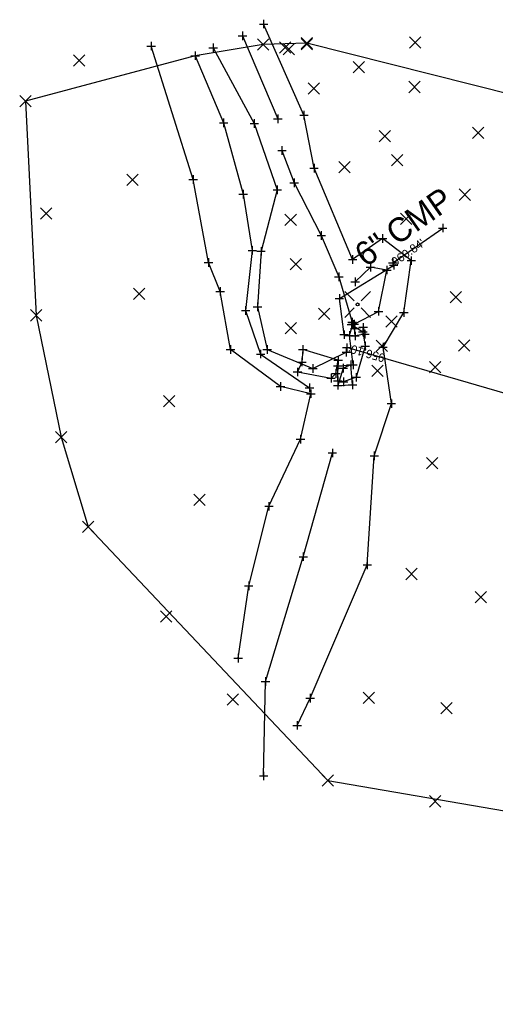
# Model space of a CAD drawing. Extents: x 160138 to 160780, y 488720 to 491073.
# Drawn here: x 160311.4 to 160367.2, y 489628.9 to 489744.3 of the extents above; entities that cross this region are included whole.
import ezdxf

# ---------------------------------------------------------------- set-up
doc = ezdxf.new("R2010")
doc.units = 0
for name, color, linetype in [('_CIVIL_CONSTRUCTION', 7, 'Continuous'), ('DR_X_Storm_Sewer', 7, 'Continuous'), ('DR_X_Text', 7, 'Continuous'), ('RD_X_Concrete_Pad', 7, 'Continuous'), ('RS_Raster1', 7, 'Continuous'), ('RW_X_CL_100_Bearings', 7, 'Continuous'), ('RW_X_CL_100_Stations', 7, 'Continuous'), ('SC_Scratch1', 7, 'Continuous'), ('SV_P_Control_Cells_Set', 7, 'Continuous'), ('SV_P_Mon_Cells_Set', 7, 'Continuous'), ('SV_X_Mon_Cells_Found', 7, 'Continuous'), ('SV_X_Random_Point', 7, 'Continuous'), ('SV_X_Terrain_Boundary', 7, 'Continuous')]:
    doc.layers.add(name, color=color, linetype=linetype)

msp = doc.modelspace()

# ---------------------------------------------------------------- linework, layer by layer
at = {"layer": '_CIVIL_CONSTRUCTION'}
for p, q in [((160339.33, 489740.77), (160340.67, 489742.1)), ((160339.33, 489742.1), (160340.67, 489740.77)), ((160344.44, 489740.93), (160345.77, 489742.26)), ((160344.44, 489742.26), (160345.77, 489740.93)), ((160344.45, 489740.81), (160345.79, 489742.14)), ((160344.45, 489742.14), (160345.79, 489740.81)), ((160357.15, 489741.01), (160358.48, 489742.35)), ((160357.15, 489742.35), (160358.48, 489741.01)), ((160341.91, 489740.44), (160343.25, 489741.77)), ((160341.91, 489741.77), (160343.25, 489740.44)), ((160342.34, 489740.23), (160343.67, 489741.57)), ((160342.34, 489741.57), (160343.67, 489740.23)), ((160317.74, 489738.89), (160319.08, 489740.22)), ((160317.74, 489740.22), (160319.08, 489738.89)), ((160350.55, 489738.12), (160351.89, 489739.46)), ((160350.55, 489739.46), (160351.89, 489738.12)), ((160345.26, 489735.61), (160346.59, 489736.94)), ((160345.26, 489736.94), (160346.59, 489735.61)), ((160357.09, 489735.79), (160358.42, 489737.13)), ((160357.09, 489737.13), (160358.42, 489735.79)), ((160311.44, 489734.13), (160312.77, 489735.46)), ((160311.44, 489735.46), (160312.77, 489734.13)), ((160364.56, 489730.41), (160365.89, 489731.75)), ((160364.56, 489731.75), (160365.89, 489730.41)), ((160353.6, 489730.03), (160354.94, 489731.36)), ((160353.6, 489731.36), (160354.94, 489730.03)), ((160355.03, 489727.22), (160356.37, 489728.55)), ((160355.03, 489728.55), (160356.37, 489727.22)), ((160348.88, 489726.4), (160350.21, 489727.73)), ((160348.88, 489727.73), (160350.21, 489726.4)), ((160323.99, 489724.93), (160325.32, 489726.26)), ((160323.99, 489726.26), (160325.32, 489724.93)), ((160362.99, 489723.17), (160364.32, 489724.51)), ((160362.99, 489724.51), (160364.32, 489723.17)), ((160313.87, 489720.98), (160315.2, 489722.31)), ((160313.87, 489722.31), (160315.2, 489720.98)), ((160342.55, 489720.24), (160343.89, 489721.57)), ((160342.55, 489721.57), (160343.89, 489720.24)), ((160356.09, 489720.33), (160357.42, 489721.67)), ((160356.09, 489721.67), (160357.42, 489720.33)), ((160343.15, 489715.03), (160344.49, 489716.37)), ((160343.15, 489716.37), (160344.49, 489715.03)), ((160324.77, 489711.56), (160326.1, 489712.9)), ((160324.77, 489712.9), (160326.1, 489711.56)), ((160361.94, 489711.16), (160363.27, 489712.49)), ((160361.94, 489712.49), (160363.27, 489711.16)), ((160312.69, 489709.04), (160314.02, 489710.37)), ((160312.69, 489710.37), (160314.02, 489709.04)), ((160346.47, 489709.21), (160347.8, 489710.55)), ((160346.47, 489710.55), (160347.8, 489709.21)), ((160354.39, 489708.31), (160355.72, 489709.65)), ((160354.39, 489709.65), (160355.72, 489708.31)), ((160342.58, 489707.53), (160343.91, 489708.86)), ((160342.58, 489708.86), (160343.91, 489707.53)), ((160353.25, 489705.47), (160354.58, 489706.81)), ((160353.25, 489706.81), (160354.58, 489705.47)), ((160362.89, 489705.51), (160364.22, 489706.84)), ((160362.89, 489706.84), (160364.22, 489705.51)), ((160352.74, 489702.54), (160354.07, 489703.88)), ((160352.74, 489703.88), (160354.07, 489702.54)), ((160359.51, 489702.97), (160360.84, 489704.3)), ((160359.51, 489704.3), (160360.84, 489702.97)), ((160328.3, 489698.99), (160329.64, 489700.32)), ((160328.3, 489700.32), (160329.64, 489698.99)), ((160315.62, 489694.76), (160316.96, 489696.09)), ((160315.62, 489696.09), (160316.96, 489694.76)), ((160359.14, 489691.72), (160360.48, 489693.06)), ((160359.14, 489693.06), (160360.48, 489691.72)), ((160331.86, 489687.41), (160333.19, 489688.74)), ((160331.86, 489688.74), (160333.19, 489687.41)), ((160318.81, 489684.26), (160320.14, 489685.6)), ((160318.81, 489685.6), (160320.14, 489684.26)), ((160356.71, 489678.73), (160358.05, 489680.06)), ((160356.71, 489680.06), (160358.05, 489678.73)), ((160364.87, 489676.02), (160366.2, 489677.36)), ((160364.87, 489677.36), (160366.2, 489676.02)), ((160327.96, 489673.74), (160329.29, 489675.07)), ((160327.96, 489675.07), (160329.29, 489673.74)), ((160335.76, 489664.03), (160337.1, 489665.37)), ((160335.76, 489665.37), (160337.1, 489664.03)), ((160351.73, 489664.21), (160353.06, 489665.54)), ((160351.73, 489665.54), (160353.06, 489664.21)), ((160360.83, 489663.01), (160362.16, 489664.34)), ((160360.83, 489664.34), (160362.16, 489663.01)), ((160346.9, 489654.53), (160348.23, 489655.87)), ((160346.9, 489655.87), (160348.23, 489654.53)), ((160359.49, 489652.09), (160360.82, 489653.43)), ((160359.49, 489653.43), (160360.82, 489652.09))]:
    msp.add_line(p, q, dxfattribs=at)
at = {"layer": 'DR_X_Storm_Sewer'}
for p, q in [((160355.2, 489715.85), (160361.05, 489719.93)), ((160416.53, 489686.63), (160349.81, 489705.92))]:
    msp.add_line(p, q, dxfattribs=at)
at = {"layer": 'RD_X_Concrete_Pad'}
msp.add_lwpolyline([(160347.95, 489702.35), (160348.52, 489702.88), (160348.8, 489704.46), (160344.64, 489705.72), (160344.53, 489704.23), (160344.01, 489703.07)], close=True, dxfattribs=at)
at = {"layer": 'RS_Raster1'}
for p, q in [((160360.55, 489719.93), (160361.55, 489719.93)), ((160361.05, 489720.43), (160361.05, 489719.43)), ((160361.05, 489719.93), (160361.05, 489719.93)), ((160354.7, 489715.85), (160355.7, 489715.85)), ((160355.2, 489716.35), (160355.2, 489715.35)), ((160355.2, 489715.85), (160355.2, 489715.85)), ((160349.81, 489706.42), (160349.81, 489705.42)), ((160349.31, 489705.92), (160350.31, 489705.92)), ((160349.81, 489705.92), (160349.81, 489705.92))]:
    msp.add_line(p, q, dxfattribs=at)
at = {"layer": 'RW_X_CL_100_Bearings'}
for points in [[(160350.77, 489707.29), (160350.72, 489708.17), (160351.73, 489708.3), (160351.93, 489707.49)], [(160349.37, 489703.52), (160348.75, 489701.5), (160350.46, 489701.56), (160350.27, 489703.9)]]:
    msp.add_lwpolyline(points, close=True, dxfattribs=at)
at = {"layer": 'RW_X_CL_100_Stations'}
msp.add_lwpolyline([(160350.35, 489708.64), (160351.68, 489707.77), (160351.95, 489706.08), (160350.9, 489702.44), (160349.43, 489701.91), (160348.74, 489702.04), (160348.75, 489703.79), (160350.53, 489703.91), (160350.1, 489707.34), (160350.52, 489708.65)], close=True, dxfattribs=at)
at = {"layer": 'SV_P_Control_Cells_Set'}
for points in [[(160343.99, 489661.66), (160345.5, 489664.84), (160352.21, 489680.48), (160353.03, 489693.23), (160355.03, 489699.36), (160354.05, 489705.99), (160356.49, 489710.03), (160357.37, 489716.11), (160353.98, 489718.71), (160350.49, 489716.24), (160345.96, 489726.95), (160344.78, 489733.16), (160340.05, 489743.84)], [(160337.56, 489742.45), (160341.71, 489732.74)], [(160337.06, 489669.53), (160338.3, 489678.01), (160340.67, 489687.33), (160344.38, 489695.18), (160345.59, 489700.52), (160342.03, 489701.36), (160336.17, 489705.71), (160334.96, 489712.51), (160333.59, 489715.9), (160331.79, 489725.62), (160326.86, 489741.26)], [(160332.02, 489740.13), (160335.36, 489732.25), (160337.64, 489723.89), (160338.72, 489717.32), (160337.94, 489710.28), (160339.7, 489705.17), (160345.42, 489701.2)], [(160342.2, 489729.01), (160343.62, 489725.24), (160346.81, 489719.05), (160348.86, 489714.22), (160350.44, 489708.92)], [(160350.68, 489708.66), (160353.52, 489710.17), (160354.49, 489715.01), (160352.57, 489715.35), (160350.79, 489713.62)]]:
    msp.add_lwpolyline(points, dxfattribs=at)
at = {"layer": 'SV_P_Mon_Cells_Set'}
for points in [[(160334.14, 489741.04), (160338.95, 489732.19), (160341.65, 489724.41), (160339.74, 489717.21), (160339.32, 489710.69), (160340.46, 489705.7), (160345.81, 489703.48), (160349.74, 489705.38)], [(160349.5, 489707.44), (160348.93, 489711.69), (160355.3, 489715.57)], [(160340.05, 489655.73), (160340.26, 489666.8), (160344.7, 489681.42), (160348.11, 489693.58)]]:
    msp.add_lwpolyline(points, dxfattribs=at)
at = {"layer": 'SV_X_Mon_Cells_Found'}
for p, q in [((160349.56, 489712.49), (160350.65, 489711.4)), ((160351.49, 489711.4), (160352.58, 489712.49)), ((160349.56, 489709.47), (160350.65, 489710.57)), ((160351.49, 489710.57), (160352.58, 489709.47))]:
    msp.add_line(p, q, dxfattribs=at)
msp.add_circle((160351.07, 489710.99), 0.17, dxfattribs=at)
at = {"layer": 'SV_X_Random_Point'}
for p, q in [((160340.05, 489744.34), (160340.05, 489743.34)), ((160339.55, 489743.84), (160340.55, 489743.84)), ((160340.05, 489743.84), (160340.05, 489743.84)), ((160337.06, 489742.45), (160338.06, 489742.45)), ((160337.56, 489742.95), (160337.56, 489741.95)), ((160337.56, 489742.45), (160337.56, 489742.45)), ((160326.36, 489741.26), (160327.36, 489741.26)), ((160326.86, 489741.76), (160326.86, 489740.76)), ((160326.86, 489741.26), (160326.86, 489741.26)), ((160333.64, 489741.04), (160334.64, 489741.04)), ((160334.14, 489741.54), (160334.14, 489740.54)), ((160334.14, 489741.04), (160334.14, 489741.04)), ((160331.52, 489740.13), (160332.52, 489740.13)), ((160332.02, 489740.63), (160332.02, 489739.63)), ((160332.02, 489740.13), (160332.02, 489740.13)), ((160335.36, 489732.75), (160335.36, 489731.75)), ((160338.95, 489732.69), (160338.95, 489731.69)), ((160341.21, 489732.74), (160342.21, 489732.74)), ((160341.71, 489733.24), (160341.71, 489732.24)), ((160341.71, 489732.74), (160341.71, 489732.74)), ((160344.28, 489733.16), (160345.28, 489733.16)), ((160344.78, 489733.66), (160344.78, 489732.66)), ((160344.78, 489733.16), (160344.78, 489733.16)), ((160334.86, 489732.25), (160335.86, 489732.25)), ((160335.36, 489732.25), (160335.36, 489732.25)), ((160338.45, 489732.19), (160339.45, 489732.19)), ((160338.95, 489732.19), (160338.95, 489732.19)), ((160342.2, 489729.51), (160342.2, 489728.51)), ((160341.7, 489729.01), (160342.7, 489729.01)), ((160342.2, 489729.01), (160342.2, 489729.01)), ((160345.46, 489726.95), (160346.46, 489726.95)), ((160345.96, 489727.45), (160345.96, 489726.45)), ((160345.96, 489726.95), (160345.96, 489726.95)), ((160331.79, 489726.12), (160331.79, 489725.12)), ((160343.62, 489725.74), (160343.62, 489724.74)), ((160331.29, 489725.62), (160332.29, 489725.62)), ((160331.79, 489725.62), (160331.79, 489725.62)), ((160341.65, 489724.91), (160341.65, 489723.91)), ((160343.12, 489725.24), (160344.12, 489725.24)), ((160343.62, 489725.24), (160343.62, 489725.24)), ((160337.14, 489723.89), (160338.14, 489723.89)), ((160337.64, 489724.39), (160337.64, 489723.39)), ((160337.64, 489723.89), (160337.64, 489723.89)), ((160341.15, 489724.41), (160342.15, 489724.41)), ((160341.65, 489724.41), (160341.65, 489724.41)), ((160346.31, 489719.05), (160347.31, 489719.05)), ((160346.81, 489719.55), (160346.81, 489718.55)), ((160346.81, 489719.05), (160346.81, 489719.05)), ((160353.98, 489719.21), (160353.98, 489718.21)), ((160338.72, 489717.82), (160338.72, 489716.82)), ((160339.74, 489717.71), (160339.74, 489716.71)), ((160353.48, 489718.71), (160354.48, 489718.71)), ((160353.98, 489718.71), (160353.98, 489718.71)), ((160338.22, 489717.32), (160339.22, 489717.32)), ((160338.72, 489717.32), (160338.72, 489717.32)), ((160339.24, 489717.21), (160340.24, 489717.21)), ((160339.74, 489717.21), (160339.74, 489717.21)), ((160350.49, 489716.74), (160350.49, 489715.74)), ((160357.37, 489716.61), (160357.37, 489715.61)), ((160333.09, 489715.9), (160334.09, 489715.9)), ((160333.59, 489716.4), (160333.59, 489715.4)), ((160333.59, 489715.9), (160333.59, 489715.9)), ((160349.99, 489716.24), (160350.99, 489716.24)), ((160350.49, 489716.24), (160350.49, 489716.24)), ((160352.07, 489715.35), (160353.07, 489715.35)), ((160352.57, 489715.85), (160352.57, 489714.85)), ((160352.57, 489715.35), (160352.57, 489715.35)), ((160354.49, 489715.51), (160354.49, 489714.51)), ((160354.8, 489715.57), (160355.8, 489715.57)), ((160355.3, 489716.07), (160355.3, 489715.07)), ((160355.3, 489715.57), (160355.3, 489715.57)), ((160356.87, 489716.11), (160357.87, 489716.11)), ((160357.37, 489716.11), (160357.37, 489716.11)), ((160348.36, 489714.22), (160349.36, 489714.22)), ((160348.86, 489714.72), (160348.86, 489713.72)), ((160348.86, 489714.22), (160348.86, 489714.22)), ((160353.99, 489715.01), (160354.99, 489715.01)), ((160354.49, 489715.01), (160354.49, 489715.01)), ((160334.96, 489713.01), (160334.96, 489712.01)), ((160350.29, 489713.62), (160351.29, 489713.62)), ((160350.79, 489714.12), (160350.79, 489713.12)), ((160350.79, 489713.62), (160350.79, 489713.62)), ((160334.46, 489712.51), (160335.46, 489712.51)), ((160334.96, 489712.51), (160334.96, 489712.51)), ((160348.93, 489712.19), (160348.93, 489711.19)), ((160337.94, 489710.78), (160337.94, 489709.78)), ((160338.82, 489710.69), (160339.82, 489710.69)), ((160339.32, 489711.19), (160339.32, 489710.19)), ((160339.32, 489710.69), (160339.32, 489710.69)), ((160348.43, 489711.69), (160349.43, 489711.69)), ((160348.93, 489711.69), (160348.93, 489711.69)), ((160353.52, 489710.67), (160353.52, 489709.67)), ((160337.44, 489710.28), (160338.44, 489710.28)), ((160337.94, 489710.28), (160337.94, 489710.28)), ((160353.02, 489710.17), (160354.02, 489710.17)), ((160353.52, 489710.17), (160353.52, 489710.17)), ((160355.99, 489710.03), (160356.99, 489710.03)), ((160356.49, 489710.53), (160356.49, 489709.53)), ((160356.49, 489710.03), (160356.49, 489710.03)), ((160349.85, 489708.64), (160350.85, 489708.64)), ((160349.94, 489708.92), (160350.94, 489708.92)), ((160350.02, 489708.65), (160351.02, 489708.65)), ((160350.18, 489708.66), (160351.18, 489708.66)), ((160350.35, 489709.14), (160350.35, 489708.14)), ((160350.35, 489708.64), (160350.35, 489708.64)), ((160350.44, 489709.42), (160350.44, 489708.42)), ((160350.44, 489708.92), (160350.44, 489708.92)), ((160350.52, 489709.15), (160350.52, 489708.15)), ((160350.52, 489708.65), (160350.52, 489708.65)), ((160350.68, 489709.16), (160350.68, 489708.16)), ((160350.68, 489708.66), (160350.68, 489708.66)), ((160350.72, 489708.67), (160350.72, 489707.67)), ((160351.73, 489708.8), (160351.73, 489707.8)), ((160349, 489707.44), (160350, 489707.44)), ((160349.5, 489707.94), (160349.5, 489706.94)), ((160349.5, 489707.44), (160349.5, 489707.44)), ((160349.6, 489707.34), (160350.6, 489707.34)), ((160350.1, 489707.84), (160350.1, 489706.84)), ((160350.1, 489707.34), (160350.1, 489707.34)), ((160350.22, 489708.17), (160351.22, 489708.17)), ((160350.27, 489707.29), (160351.27, 489707.29)), ((160350.72, 489708.17), (160350.72, 489708.17)), ((160350.77, 489707.79), (160350.77, 489706.79)), ((160350.77, 489707.29), (160350.77, 489707.29)), ((160351.18, 489707.77), (160352.18, 489707.77)), ((160351.23, 489708.3), (160352.23, 489708.3)), ((160351.43, 489707.49), (160352.43, 489707.49)), ((160351.68, 489708.27), (160351.68, 489707.27)), ((160351.68, 489707.77), (160351.68, 489707.77)), ((160351.73, 489708.3), (160351.73, 489708.3)), ((160351.93, 489707.99), (160351.93, 489706.99)), ((160351.93, 489707.49), (160351.93, 489707.49)), ((160336.17, 489706.21), (160336.17, 489705.21)), ((160340.46, 489706.2), (160340.46, 489705.2)), ((160344.64, 489706.22), (160344.64, 489705.22)), ((160351.45, 489706.08), (160352.45, 489706.08)), ((160351.95, 489706.58), (160351.95, 489705.58)), ((160351.95, 489706.08), (160351.95, 489706.08)), ((160354.05, 489706.49), (160354.05, 489705.49)), ((160335.67, 489705.71), (160336.67, 489705.71)), ((160336.17, 489705.71), (160336.17, 489705.71)), ((160339.2, 489705.17), (160340.2, 489705.17)), ((160339.7, 489705.67), (160339.7, 489704.67)), ((160339.7, 489705.17), (160339.7, 489705.17)), ((160339.96, 489705.7), (160340.96, 489705.7)), ((160340.46, 489705.7), (160340.46, 489705.7)), ((160344.14, 489705.72), (160345.14, 489705.72)), ((160344.64, 489705.72), (160344.64, 489705.72)), ((160348.8, 489704.96), (160348.8, 489703.96)), ((160349.24, 489705.38), (160350.24, 489705.38)), ((160349.74, 489705.88), (160349.74, 489704.88)), ((160349.74, 489705.38), (160349.74, 489705.38)), ((160353.55, 489705.99), (160354.55, 489705.99)), ((160354.05, 489705.99), (160354.05, 489705.99)), ((160344.03, 489704.23), (160345.03, 489704.23)), ((160344.53, 489704.73), (160344.53, 489703.73)), ((160344.53, 489704.23), (160344.53, 489704.23)), ((160345.81, 489703.98), (160345.81, 489702.98)), ((160348.25, 489703.79), (160349.25, 489703.79)), ((160348.3, 489704.46), (160349.3, 489704.46)), ((160348.75, 489704.29), (160348.75, 489703.29)), ((160348.75, 489703.79), (160348.75, 489703.79)), ((160348.8, 489704.46), (160348.8, 489704.46)), ((160349.37, 489704.02), (160349.37, 489703.02)), ((160349.77, 489703.9), (160350.77, 489703.9)), ((160350.03, 489703.91), (160351.03, 489703.91)), ((160350.27, 489704.4), (160350.27, 489703.4)), ((160350.27, 489703.9), (160350.27, 489703.9)), ((160350.53, 489704.41), (160350.53, 489703.41)), ((160350.53, 489703.91), (160350.53, 489703.91)), ((160343.51, 489703.07), (160344.51, 489703.07)), ((160344.01, 489703.57), (160344.01, 489702.57)), ((160344.01, 489703.07), (160344.01, 489703.07)), ((160345.31, 489703.48), (160346.31, 489703.48)), ((160345.81, 489703.48), (160345.81, 489703.48)), ((160347.95, 489702.85), (160347.95, 489701.85)), ((160348.02, 489702.88), (160349.02, 489702.88)), ((160348.52, 489703.38), (160348.52, 489702.38)), ((160348.52, 489702.88), (160348.52, 489702.88)), ((160348.87, 489703.52), (160349.87, 489703.52)), ((160349.37, 489703.52), (160349.37, 489703.52)), ((160350.9, 489702.94), (160350.9, 489701.94)), ((160342.03, 489701.86), (160342.03, 489700.86)), ((160345.42, 489701.7), (160345.42, 489700.7)), ((160347.45, 489702.35), (160348.45, 489702.35)), ((160347.95, 489702.35), (160347.95, 489702.35)), ((160348.24, 489702.04), (160349.24, 489702.04)), ((160348.25, 489701.5), (160349.25, 489701.5)), ((160348.74, 489702.54), (160348.74, 489701.54)), ((160348.74, 489702.04), (160348.74, 489702.04)), ((160348.75, 489702), (160348.75, 489701)), ((160348.75, 489701.5), (160348.75, 489701.5)), ((160348.93, 489701.91), (160349.93, 489701.91)), ((160349.43, 489702.41), (160349.43, 489701.41)), ((160349.43, 489701.91), (160349.43, 489701.91)), ((160349.96, 489701.56), (160350.96, 489701.56)), ((160350.4, 489702.44), (160351.4, 489702.44)), ((160350.46, 489702.06), (160350.46, 489701.06)), ((160350.46, 489701.56), (160350.46, 489701.56)), ((160350.9, 489702.44), (160350.9, 489702.44)), ((160341.53, 489701.36), (160342.53, 489701.36)), ((160342.03, 489701.36), (160342.03, 489701.36)), ((160344.92, 489701.2), (160345.92, 489701.2)), ((160345.09, 489700.52), (160346.09, 489700.52)), ((160345.42, 489701.2), (160345.42, 489701.2)), ((160345.59, 489701.02), (160345.59, 489700.02)), ((160345.59, 489700.52), (160345.59, 489700.52)), ((160354.53, 489699.36), (160355.53, 489699.36)), ((160355.03, 489699.86), (160355.03, 489698.86)), ((160355.03, 489699.36), (160355.03, 489699.36)), ((160344.38, 489695.68), (160344.38, 489694.68)), ((160343.88, 489695.18), (160344.88, 489695.18)), ((160344.38, 489695.18), (160344.38, 489695.18)), ((160347.61, 489693.58), (160348.61, 489693.58)), ((160348.11, 489694.08), (160348.11, 489693.08)), ((160348.11, 489693.58), (160348.11, 489693.58)), ((160353.03, 489693.73), (160353.03, 489692.73)), ((160352.53, 489693.23), (160353.53, 489693.23)), ((160353.03, 489693.23), (160353.03, 489693.23)), ((160340.67, 489687.83), (160340.67, 489686.83)), ((160340.17, 489687.33), (160341.17, 489687.33)), ((160340.67, 489687.33), (160340.67, 489687.33)), ((160344.7, 489681.92), (160344.7, 489680.92)), ((160344.2, 489681.42), (160345.2, 489681.42)), ((160344.7, 489681.42), (160344.7, 489681.42)), ((160352.21, 489680.98), (160352.21, 489679.98)), ((160351.71, 489680.48), (160352.71, 489680.48)), ((160352.21, 489680.48), (160352.21, 489680.48)), ((160338.3, 489678.51), (160338.3, 489677.51)), ((160337.8, 489678.01), (160338.8, 489678.01)), ((160338.3, 489678.01), (160338.3, 489678.01)), ((160336.56, 489669.53), (160337.56, 489669.53)), ((160337.06, 489670.03), (160337.06, 489669.03)), ((160337.06, 489669.53), (160337.06, 489669.53)), ((160339.76, 489666.8), (160340.76, 489666.8)), ((160340.26, 489667.3), (160340.26, 489666.3)), ((160340.26, 489666.8), (160340.26, 489666.8)), ((160345, 489664.84), (160346, 489664.84)), ((160345.5, 489665.34), (160345.5, 489664.34)), ((160345.5, 489664.84), (160345.5, 489664.84)), ((160343.99, 489662.16), (160343.99, 489661.16)), ((160343.49, 489661.66), (160344.49, 489661.66)), ((160343.99, 489661.66), (160343.99, 489661.66)), ((160339.55, 489655.73), (160340.55, 489655.73)), ((160340.05, 489656.23), (160340.05, 489655.23)), ((160340.05, 489655.73), (160340.05, 489655.73))]:
    msp.add_line(p, q, dxfattribs=at)
at = {"layer": 'SV_X_Terrain_Boundary'}
msp.add_lwpolyline([(160560.41, 489729.32), (160491.05, 489700.61), (160398.91, 489721.41), (160369.48, 489735.48), (160345.1, 489741.59), (160340, 489741.44), (160332.02, 489740.13), (160312.1, 489734.79), (160313.36, 489709.7), (160316.29, 489695.42), (160319.47, 489684.93), (160347.56, 489655.2), (160408.83, 489644.7), (160473.47, 489628.86), (160504.76, 489630.54), (160514.91, 489637.89), (160547.86, 489638.24)], dxfattribs=at)

# ---------------------------------------------------------------- texts
at = {"layer": 'DR_X_Text'}
msp.add_text('6" CMP', height=2.8, rotation=34.8662, dxfattribs=at).set_placement((160352.02, 489715.28))
at = {"layer": 'SC_Scratch1'}
for s, rotation, p in [("960.84'", 34.8662, (160355.48, 489715.44)), ("956.10'", 163.8709, (160354.36, 489705.13))]:
    msp.add_text(s, height=1, rotation=rotation, dxfattribs=at).set_placement(p)

doc.saveas('drawing.dxf')
